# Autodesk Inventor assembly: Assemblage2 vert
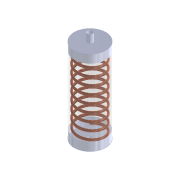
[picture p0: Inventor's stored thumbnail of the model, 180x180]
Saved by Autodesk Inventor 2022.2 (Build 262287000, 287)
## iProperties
Created: 2016-10
Part Number: Assemblage2 vert
Document SubType Name: Assembly
Designer: 18907419
Author: 18907419
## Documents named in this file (4)
- C:\Users\18907419\Desktop\frigo\Assemblage2 vert.iam
- C:\Users\18907419\Desktop\frigo\Pièce5.ipt
- C:\Users\18907419\Desktop\frigo\Pièce4.ipt
- C:\Users\18907419\Desktop\frigo\Pièce1 vert.ipt
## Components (4 placed, 3 different names)
1. Pièce5:1
2. Pièce4:1
3. Pièce5:2
4. Pièce1 vert:1
